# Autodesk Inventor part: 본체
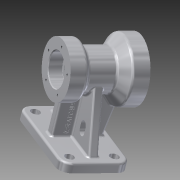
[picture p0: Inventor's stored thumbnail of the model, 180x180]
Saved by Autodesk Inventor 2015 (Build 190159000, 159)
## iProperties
Created: 2015-08
Part Number: 본체
Material: 알루미늄 6061
Document SubType Name: Modeling
Designer: PHO-1
Density: 2.7 g/cm^3
Appearance: 알루미늄 - 평지
Mass: 1041.81 g
Surface Area: 750.374 cm^2
Volume: 385.854 cm^3
Author: PHO-1
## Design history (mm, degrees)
sketch "스케치2"
  geometry: L1 (0, 0)-(-45, 0); L2 (-45, 0)-(-45, 35); L3 (-45, 35)-(-27.887, 35); L4 (-23.557, 32.5)-(-21.247, 28.5); L5 (-25, 35)-(-4.793, 35); L6 (0, 0)-(45, 0); L7 (45, 0)-(45, 40); L8 (45, 40)-(27.332, 40); L9 (23.501, 38.214)-(14.751, 27.786); L10 (-16.917, 26)-(10.921, 26); A1 r 5 centre (-27.887, 30) between (-23.557, 32.5) and (-27.887, 35); A2 r 5 centre (-16.917, 31) between (-21.247, 28.5) and (-16.917, 26); A3 r 5 centre (10.921, 31) between (10.921, 26) and (14.751, 27.786); A4 r 5 centre (27.332, 35) between (27.332, 40) and (23.501, 38.214); 1 further point
  constraints: 20 end point, 8 point on circle, 8 tangent, 4 centre point, 4 horizontal, 4 perpendicular, 4 point on line, 3 equal radius
  dimensions: "d3" = 45 distance of L1.start L1.end; "d4" = 35 distance of L1.end L2.end; "d5" = 20 distance of L2.end L5.start; "d6" = 60 deg angle of L4 L5; "d7" = 45 distance of L1.start L6.end; "d8" = 40 distance of L6.end L7.end; "d9" = 20 distance of L7.end point (25, 40); "d10" = 130 deg angle of L9 L8; "d11" = 26 distance between parallel lines of L10 L1; "d12" = 5 radius of A1
revolve "회전1" sketch "스케치2" stored, may be unused: angle "d13" = 90 deg
node "작업 평면1"
sketch "스케치3"
  geometry: L1 (0, 0)-(-45, 0); L2 (-45, -35)-(-45, 35) reference; L3 (-45, 0)-(-45, 61); L4 (-45, 61)-(35, 61); L5 (35, 61)-(35, -61); L6 (35, -61)-(-45, -61); L7 (-45, -61)-(-45, 61)
  constraints: 12 end point, 2 parallel, 2 perpendicular, 1 horizontal, 1 midpoint
  dimensions: "d15" = 61 distance of L1.end L3.end; "d16" = 80 distance of L5.end L6.end; "d17" = 122 distance of L4.end L5.end
extrude "돌출2" join sketch "스케치3" distance "d18" = 12; taper "d19" = 0 deg
sketch "스케치5"
  geometry: L1 (-35, 78)-(45, 78) reference; L2 (-27.332, 40)-(-45, 40) reference; L3 (45, 35)-(27.887, 35) reference; L4 (45, 78)-(35, 78); L5 (35, 78)-(35, 13.482); L6 (35, 13.482)-(-34.309, 13.482); L7 (-35, 78)-(-25, 78); L8 (-25, 78)-(-34.309, 25.204); L9 (-34.309, 25.204)-(-34.309, 13.482); L10 (-25, 78)-(35, 78); 1 further point
  constraints: 14 end point, 3 perpendicular, 2 point on line, 1 horizontal
  dimensions: "d25" = 10 distance of L1.end L4.end; "d26" = 10 distance of L1.start L7.end; "d27" = 80 deg angle of L7 L8
extrude "돌출4" join sketch "스케치5" stored distance "d28" = 12; taper "d29" = 0 deg
sketch "스케치7"
  geometry: L1 (0, 0)-(33, 0); 1 further point
  constraints: 2 end point, 1 coincident, 1 horizontal
  dimensions: "d38" = 33 distance of L1.start L1.end
hole "구멍1" sketch "스케치7" at (33, 0) diameter "d39" = 3.242; stored, may be unused: countersink angle "d43" = 90 deg, drill point angle "d45" = 118 deg; dims "d40" = 10, "d41" = 4, "d42" = 2, "d44" = 13
sketch "스케치8"
  geometry: L1 (0, 0)-(-27, 0); 1 further point
  constraints: 2 end point, 1 coincident, 1 horizontal
  dimensions: "d49" = 27 distance of L1.start L1.end
hole "구멍2" sketch "스케치8" at (-27, 0) diameter "d50" = 3.242; stored, may be unused: countersink angle "d54" = 90 deg, drill point angle "d56" = 118 deg; dims "d51" = 10, "d52" = 4, "d53" = 2, "d55" = 13
sketch "스케치9"
  geometry: L1 (-35, -34.482)-(-35, -78) reference; L2 (-35, -78)-(-19, -78); L3 (-35, -78)-(25, -78) reference; L4 (-19, -78)-(-19, -54); 4 further points
  constraints: 4 end point, 2 coincident, 1 point on line, 1 vertical, 1 other
  dimensions: "d60" = 16 distance of L1.end L2.end; "d61" = 24 distance of L2.end L4.end
feature "엠보싱1" sketch "스케치9" dims "d3" = 45, "d62" = 0.5, "d63" = 0
sketch "스케치10"
  geometry: C1 r 20 at (0, 0); 1 further point
  constraints: 1 centre point, 1 coincident
  dimensions: "d64" = 40 diameter of C1
extrude "돌출6" cut sketch "스케치10" distance "d65" = 17; taper "d66" = 0 deg
sketch "스케치11"
  geometry: C1 r 26 at (0, 0); 1 further point
  constraints: 1 centre point, 1 coincident
  dimensions: "d67" = 52 diameter of C1
extrude "돌출7" cut sketch "스케치11" distance "d68" = 20; taper "d69" = 0 deg
sketch "스케치12"
  geometry: C1 r 19 at (0, 0); 1 further point
  constraints: 1 centre point, 1 coincident
  dimensions: "d70" = 38 diameter of C1
extrude "돌출8" cut sketch "스케치12" distance "d71" = 3; taper "d72" = 0 deg
sketch "스케치13"
  geometry: C1 r 16 at (0, 0); 1 further point
  constraints: 1 centre point, 1 coincident
  dimensions: "d73" = 32 diameter of C1
extrude "돌출9" cut sketch "스케치13" stored distance "d74" = 3; taper "d75" = 0 deg
fillet "모깎기1" dims "d76" = 3
fillet "모깎기2" dims "d77" = 0.3
chamfer "모따기1" distance "d78" = 1; stored, may be unused: second distance "d79" = 2, angle "d80" = 45 deg
fillet "모깎기3" dims "d81" = 3
fillet "모깎기4" dims "d82" = 14
fillet "모깎기6" dims "d84" = 3
fillet "모깎기7" dims "d85" = 3
fillet "모깎기8" dims "d86" = 3
sketch "스케치14"
  geometry: L1 (-31, -61)-(21, -61) reference; L2 (-5, -61)-(21, -61); L3 (21, -61)-(21, -47); C1 r 6 at (21, -47); 1 further point
  constraints: 4 end point, 1 centre point, 1 coincident, 1 horizontal, 1 midpoint, 1 perpendicular
  dimensions: "d87" = 26 distance of L2.start L1.end (derived); "d88" = 14 distance of L1.end L3.end; "d89" = 12 diameter of C1
extrude "돌출10" cut sketch "스케치14" distance "d90" = 12; taper "d91" = 0 deg
node "작업 평면2"
sketch "스케치16"
  geometry: L1 (51, 78)-(25.091, 6.815); A1 r 26 centre (0, 0) between (-8.069, 24.716) and (8.069, 24.716) reference; 2 further points
  constraints: 2 end point, 1 point on circle
feature "리브1" sketch "스케치16" dims "d106" = 1, "d107" = 12, "d108" = 0, "d109" = 0, "d110" = 1, "d111" = 1
fillet "모깎기9" dims "d112" = 3
fillet "모깎기10" dims "d113" = 3
fillet "모깎기11" dims "d114" = 3
fillet "모깎기12" dims "d115" = 3
sketch "스케치17"
  geometry: L1 (-15, -56)-(-15, 38) reference; L2 (-15, -9)-(15, -9); L3 (21, 9)-(15, 9); L4 (15, 21)-(21, 21); A1 r 6 centre (21, 15) between (21, 9) and (21, 21); A2 r 6 centre (15, 15) between (15, 21) and (15, 9); 1 further point
  constraints: 6 end point, 4 point on circle, 2 centre point, 1 horizontal, 1 midpoint, 1 tangent
  dimensions: "d116" = 30 distance of L2.start L2.end
extrude "돌출11" cut sketch "스케치17" stored distance "d120" = 10; taper "d121" = 0 deg
node "솔리드2"
pattern_circular "원형 패턴1" dims angle "d47" = 360 deg
pattern_circular "원형 패턴2" dims angle "d58" = 360 deg
pattern_linear "직사각형 패턴1" dims "d94" = 52, "d97" = 94
mirror "대칭2"
mirror "대칭3"
other parameters: "d35" = 12, "d102" = -5, "d118" = 12, "d119" = 12
